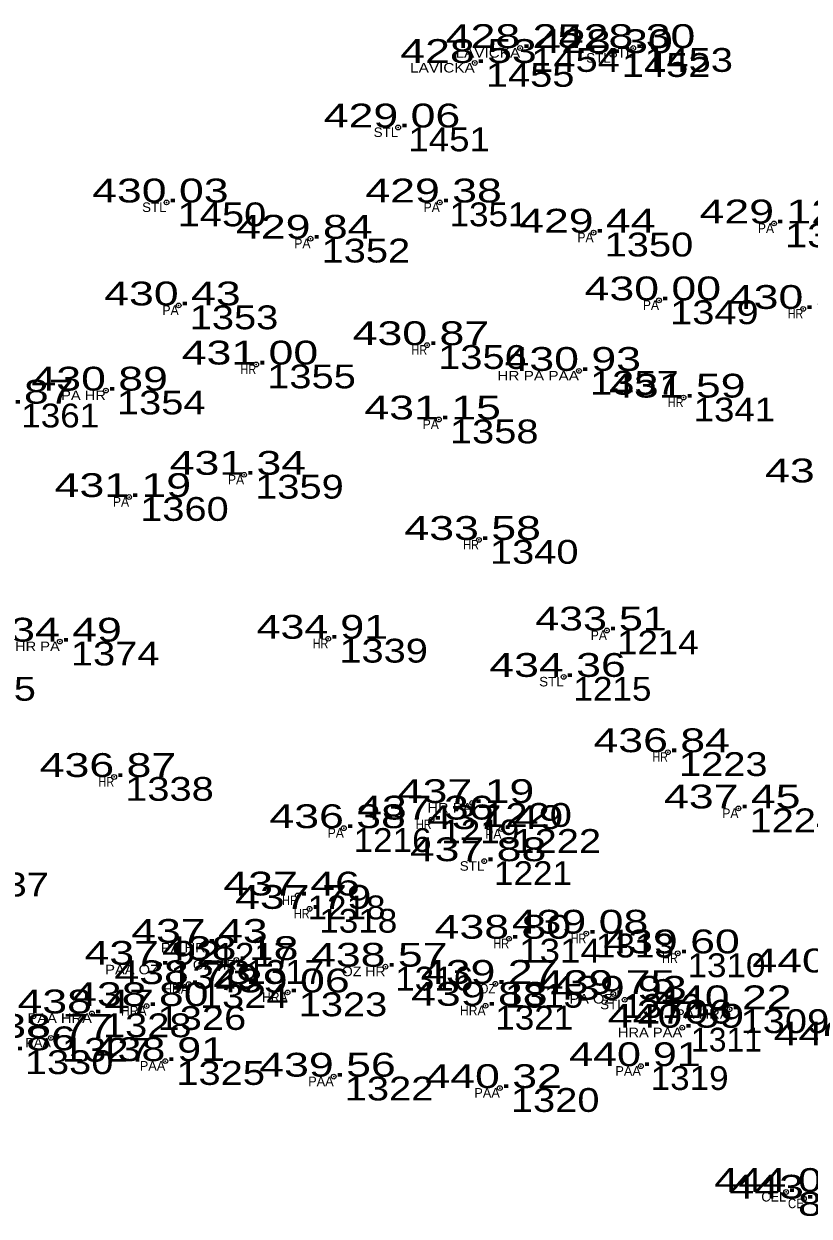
# Model space of a CAD drawing. Extents: x -639390 to -639074, y -1138747 to -1138358.
# Drawn here: x -639261.04 to -639236.32, y -1138641.21 to -1138603.69 of the extents above; entities that cross this region are included whole.
import ezdxf
from ezdxf.enums import TextEntityAlignment as Align

# ---------------------------------------------------------------- set-up
doc = ezdxf.new("R2010")
doc.units = 0
doc.header["$LTSCALE"] = 0.3
doc.header["$PDMODE"] = 32
doc.header["$PDSIZE"] = 0.15
for name, color, linetype in [('11', 7, 'Continuous'), ('12', 7, 'Continuous'), ('13', 7, 'Continuous'), ('57', 7, 'Continuous')]:
    doc.layers.add(name, color=color, linetype=linetype)

msp = doc.modelspace()

# ---------------------------------------------------------------- linework, layer by layer
at = {"layer": '11'}
for p in [(-639245.42, -1138604.45), (-639242.57, -1138604.61), (-639241.86, -1138604.45), (-639246.85, -1138604.92), (-639249.26, -1138606.95), (-639256.55, -1138609.31), (-639247.95, -1138609.31), (-639243.11, -1138610.26), (-639237.43, -1138609.97), (-639252.02, -1138610.45), (-639256.17, -1138612.55), (-639241.05, -1138612.39), (-639236.51, -1138612.66), (-639248.35, -1138613.8), (-639253.73, -1138614.41), (-639243.57, -1138614.61), (-639258.46, -1138615.23), (-639240.28, -1138615.45), (-639247.98, -1138616.14), (-639254.11, -1138617.88), (-639257.73, -1138618.58), (-639246.72, -1138619.93), (-639251.46, -1138623.04), (-639242.69, -1138622.78), (-639259.91, -1138623.13), (-639244.05, -1138624.24), (-639240.77, -1138626.61), (-639258.2, -1138627.39), (-639246.93, -1138628.21), (-639238.55, -1138628.38), (-639250.97, -1138629), (-639248.21, -1138628.73), (-639246.01, -1138629.03), (-639246.55, -1138630.04), (-639252.42, -1138631.12), (-639252.05, -1138631.54), (-639243.34, -1138632.32), (-639255.32, -1138632.61), (-639245.77, -1138632.48), (-639254.35, -1138633.15), (-639240.46, -1138632.94), (-639256.79, -1138633.3), (-639249.66, -1138633.36), (-639255.85, -1138633.91), (-639246.2, -1138633.9), (-639252.74, -1138634.17), (-639242.49, -1138634.22), (-639257.18, -1138634.6), (-639246.51, -1138634.59), (-639242.13, -1138634.4), (-639238.83, -1138634.7), (-639258.9, -1138634.83), (-639240.32, -1138635.28), (-639260.19, -1138635.6), (-639256.59, -1138636.33), (-639241.62, -1138636.49), (-639251.29, -1138636.82), (-639246.06, -1138637.18), (-639237.05, -1138640.45), (-639236.49, -1138640.66)]:
    msp.add_point(p, dxfattribs=at)

# ---------------------------------------------------------------- texts
at = {"layer": '12'}
for s, width, p in [('428.25 ', 1.4, (-639245.42, -1138604.45)), ('428.30 ', 1.4, (-639242.57, -1138604.61)), ('428.30 ', 1.4, (-639241.86, -1138604.45)), ('428.53 ', 1.4, (-639246.85, -1138604.92)), ('429.06 ', 1.4, (-639249.259, -1138606.95)), ('430.03 ', 1.4, (-639256.55, -1138609.31)), ('429.38 ', 1.4, (-639247.95, -1138609.31)), ('429.44 ', 1.4, (-639243.11, -1138610.26)), ('429.12 ', 1.4, (-639237.43, -1138609.97)), ('429.84 ', 1.4, (-639252.02, -1138610.45)), ('430.00 ', 1.4, (-639241.05, -1138612.39)), ('430.43 ', 1.4, (-639256.17, -1138612.55)), ('430.56 ', 1.4, (-639236.509, -1138612.66)), ('430.87 ', 1.4, (-639248.35, -1138613.8)), ('431.00 ', 1.4, (-639253.73, -1138614.41)), ('430.93 ', 1.4, (-639243.57, -1138614.61)), ('430.89 ', 1.4, (-639258.46, -1138615.23)), ('431.59 ', 1.4, (-639240.28, -1138615.45)), ('430.87 ', 1.4, (-639261.43, -1138615.64)), ('431.15 ', 1.4, (-639247.98, -1138616.14)), ('431.34 ', 1.4, (-639254.11, -1138617.88)), ('431.48 ', 1.4, (-639235.37, -1138618.12)), ('431.19 ', 1.4, (-639257.73, -1138618.58)), ('433.58 ', 1.4, (-639246.72, -1138619.93)), ('433.51 ', 1.35, (-639242.689, -1138622.78)), ('434.49 ', 1.4, (-639259.91, -1138623.13)), ('434.91 ', 1.35, (-639251.459, -1138623.04)), ('434.36 ', 1.4, (-639244.049, -1138624.24)), ('436.84 ', 1.4, (-639240.77, -1138626.61)), ('436.87 ', 1.4, (-639258.2, -1138627.39)), ('437.19 ', 1.4, (-639246.93, -1138628.21)), ('437.45 ', 1.4, (-639238.55, -1138628.38)), ('436.38 ', 1.4, (-639250.97, -1138629)), ('437.36 ', 1.4, (-639248.209, -1138628.73)), ('437.49 ', 1.4, (-639246.01, -1138629.03)), ('437.88 ', 1.4, (-639246.55, -1138630.04)), ('437.46 ', 1.4, (-639252.419, -1138631.12)), ('437.79 ', 1.4, (-639252.05, -1138631.54)), ('439.08 ', 1.4, (-639243.34, -1138632.32)), ('437.43 ', 1.4, (-639255.32, -1138632.61)), ('438.80 ', 1.4, (-639245.77, -1138632.48)), ('438.18 ', 1.4, (-639254.35, -1138633.15)), ('439.60 ', 1.4, (-639240.46, -1138632.94)), ('437.92 ', 1.4, (-639256.79, -1138633.3)), ('438.57 ', 1.4, (-639249.66, -1138633.36)), ('439.27 ', 1.4, (-639246.2, -1138633.9)), ('440.33 ', 1.4, (-639235.77, -1138633.54)), ('438.73 ', 1.4, (-639255.85, -1138633.91)), ('439.06 ', 1.4, (-639252.739, -1138634.17)), ('439.75 ', 1.4, (-639242.49, -1138634.22)), ('438.80 ', 1.4, (-639257.18, -1138634.6)), ('439.88 ', 1.4, (-639246.51, -1138634.59)), ('439.93 ', 1.4, (-639242.13, -1138634.4)), ('438.47 ', 1.4, (-639258.9, -1138634.83)), ('440.22 ', 1.4, (-639238.83, -1138634.7)), ('440.59 ', 1.4, (-639240.32, -1138635.28)), ('438.77 ', 1.4, (-639260.19, -1138635.6)), ('438.86 ', 1.4, (-639261.359, -1138635.99)), ('440.94 ', 1.4, (-639235.1, -1138635.84)), ('438.91 ', 1.35, (-639256.589, -1138636.33)), ('440.91 ', 1.35, (-639241.619, -1138636.49)), ('439.56 ', 1.4, (-639251.289, -1138636.82)), ('440.32 ', 1.4, (-639246.06, -1138637.18)), ('444.01 ', 1.35, (-639237.049, -1138640.45)), ('443.83 ', 1.4, (-639236.49, -1138640.66))]:
    msp.add_text(s, height=0.75, dxfattribs=dict(at, width=width)).set_placement(p, align=Align.CENTER)
at = {"layer": '13'}
for s, width, p in [(' 1454', 1.25, (-639245.42, -1138605.2)), (' 1452', 1.25, (-639242.57, -1138605.36)), (' 1453', 1.25, (-639241.86, -1138605.2)), (' 1455', 1.25, (-639246.85, -1138605.67)), (' 1451', 1.15, (-639249.26, -1138607.7)), (' 1450', 1.25, (-639256.55, -1138610.06)), (' 1351', 1.1, (-639247.95, -1138610.06)), (' 1350', 1.25, (-639243.11, -1138611.01)), (' 1348', 1.25, (-639237.43, -1138610.72)), (' 1352', 1.25, (-639252.02, -1138611.2)), (' 1349', 1.25, (-639241.05, -1138613.14)), (' 1353', 1.25, (-639256.17, -1138613.3)), (' 1356', 1.25, (-639248.35, -1138614.55)), (' 1355', 1.25, (-639253.73, -1138615.16)), (' 1357', 1.25, (-639243.57, -1138615.36)), (' 1354', 1.25, (-639258.46, -1138615.98)), (' 1341', 1.15, (-639240.28, -1138616.2)), (' 1361', 1.1, (-639261.43, -1138616.39)), (' 1358', 1.25, (-639247.98, -1138616.89)), (' 1359', 1.25, (-639254.11, -1138618.63)), (' 1360', 1.25, (-639257.73, -1138619.33)), (' 1340', 1.25, (-639246.72, -1138620.68)), (' 1214', 1.15, (-639242.69, -1138623.53)), (' 1374', 1.25, (-639259.91, -1138623.88)), (' 1339', 1.25, (-639251.46, -1138623.79)), (' 1375', 1.25, (-639263.8, -1138624.99)), (' 1215', 1.1, (-639244.05, -1138624.99)), (' 1223', 1.25, (-639240.77, -1138627.36)), (' 1338', 1.25, (-639258.2, -1138628.14)), (' 1220', 1.25, (-639246.93, -1138628.96)), (' 1224', 1.25, (-639238.55, -1138629.13)), (' 1216', 1.1, (-639250.97, -1138629.75)), (' 1219', 1.1, (-639248.21, -1138629.48)), (' 1222', 1.25, (-639246.01, -1138629.78)), (' 1221', 1.1, (-639246.55, -1138630.79)), (' 1337', 1.25, (-639263.39, -1138631.15)), (' 1218', 1.1, (-639252.42, -1138631.87)), (' 1318', 1.1, (-639252.05, -1138632.29)), (' 1313', 1.1, (-639243.34, -1138633.07)), (' 1217', 1.1, (-639255.32, -1138633.36)), (' 1314', 1.15, (-639245.77, -1138633.23)), (' 1317', 1.1, (-639254.35, -1138633.9)), (' 1310', 1.1, (-639240.46, -1138633.69)), (' 1329', 1.25, (-639256.79, -1138634.05)), (' 1316', 1.1, (-639249.66, -1138634.11)), (' 1315', 1.1, (-639246.2, -1138634.65)), (' 1324', 1.25, (-639255.85, -1138634.66)), (' 1323', 1.25, (-639252.74, -1138634.92)), (' 1312', 1.1, (-639242.49, -1138634.97)), (' 1326', 1.25, (-639257.18, -1138635.35)), (' 1321', 1.1, (-639246.51, -1138635.34)), (' 2706', 1.35, (-639242.13, -1138635.15)), (' 1328', 1.25, (-639258.9, -1138635.58)), (' 1309', 1.25, (-639238.83, -1138635.45)), (' 1327', 1.25, (-639260.19, -1138636.35)), (' 1330', 1.25, (-639261.36, -1138636.74)), (' 1325', 1.25, (-639256.59, -1138637.08)), (' 1319', 1.1, (-639241.62, -1138637.24)), (' 1322', 1.25, (-639251.29, -1138637.57)), (' 1320', 1.25, (-639246.06, -1138637.93)), (' 84', 1.35, (-639237.05, -1138641.2))]:
    msp.add_text(s, height=0.75, dxfattribs=dict(at, width=width)).set_placement(p)
msp.add_text(' 1311', height=0.75, dxfattribs=at).set_placement((-639240.32, -1138636.03))
at = {"layer": '57'}
for s, width, p in [('LAVICKA', 1.2, (-639245.42, -1138604.75)), ('STL', 1.05, (-639242.569, -1138604.91)), ('STL', 1.05, (-639241.859, -1138604.75)), ('LAVICKA', 1.2, (-639246.85, -1138605.22)), ('STL', 1.05, (-639249.259, -1138607.25)), ('STL', 1.05, (-639256.549, -1138609.61)), ('PA', 0.95, (-639247.95, -1138609.61)), ('PA', 0.95, (-639237.43, -1138610.27)), ('PA', 0.95, (-639252.02, -1138610.75)), ('PA', 0.95, (-639243.11, -1138610.56)), ('PA', 0.95, (-639241.05, -1138612.69)), ('PA', 0.95, (-639256.17, -1138612.85)), ('HR', 0.85, (-639236.509, -1138612.96)), ('HR', 0.85, (-639248.349, -1138614.1)), ('HR', 0.85, (-639253.729, -1138614.71)), ('HR PA PAA', 1.2, (-639243.57, -1138614.91)), ('PA HR', 1.15, (-639258.459, -1138615.53)), ('HR', 0.85, (-639240.279, -1138615.75)), ('PA', 0.95, (-639247.98, -1138616.44)), ('PA', 0.95, (-639254.11, -1138618.18)), ('PA', 0.95, (-639257.73, -1138618.88)), ('HR', 0.85, (-639246.719, -1138620.23)), ('PA', 0.95, (-639242.69, -1138623.08)), ('HR PA', 1.15, (-639259.91, -1138623.43)), ('HR', 0.85, (-639251.459, -1138623.34)), ('STL', 1.05, (-639244.049, -1138624.54)), ('HR', 0.85, (-639240.769, -1138626.91)), ('HR', 0.85, (-639258.199, -1138627.69)), ('HR PA', 1.15, (-639246.93, -1138628.51)), ('PA', 0.95, (-639238.55, -1138628.68)), ('PA', 0.95, (-639250.97, -1138629.3)), ('HR', 0.85, (-639248.209, -1138629.03)), ('PA', 0.95, (-639246.01, -1138629.33)), ('STL', 1.05, (-639246.549, -1138630.34)), ('HR', 0.85, (-639252.419, -1138631.42)), ('HR', 0.85, (-639252.049, -1138631.84)), ('HR', 0.85, (-639243.339, -1138632.62)), ('PA HR', 1.15, (-639255.319, -1138632.91)), ('HR', 0.85, (-639245.769, -1138632.78)), ('HR', 0.85, (-639240.459, -1138633.24)), ('PAA OZ', 1.15, (-639256.789, -1138633.6)), ('OZ HR', 1.1, (-639254.349, -1138633.45)), ('OZ HR', 1.1, (-639249.659, -1138633.66)), ('HRA', 0.95, (-639255.85, -1138634.21)), ('HRA', 0.95, (-639252.74, -1138634.47)), ('OZ', 0.9, (-639246.199, -1138634.2)), ('PA OZ', 1.15, (-639242.489, -1138634.52)), ('HRA', 0.95, (-639257.18, -1138634.9)), ('HRA', 0.95, (-639246.51, -1138634.89)), ('STL', 1.05, (-639242.129, -1138634.7)), ('PAA HRA', 1.15, (-639258.9, -1138635.13)), ('PA HRA', 1.15, (-639238.83, -1138635)), ('HRA PAA', 1.15, (-639240.32, -1138635.58)), ('CE', 0.9, (-639236.49, -1138640.96))]:
    msp.add_text(s, height=0.3, dxfattribs=dict(at, width=width)).set_placement(p, align=Align.RIGHT)
for s, p in [('PAA', (-639260.19, -1138635.9)), ('PAA', (-639256.59, -1138636.63)), ('PAA', (-639241.62, -1138636.79)), ('PAA', (-639251.29, -1138637.12)), ('PAA', (-639246.06, -1138637.48)), ('CEL', (-639237.049, -1138640.75))]:
    msp.add_text(s, height=0.3, dxfattribs=at).set_placement(p, align=Align.RIGHT)

doc.saveas('drawing.dxf')
